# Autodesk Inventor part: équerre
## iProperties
Shininess: 64.0
Length Units: 11269
Angle Units: 11279
Time Units: 11290
Mass Units: 11283
Length Display Precision: 3
Angle Display Precision: 2
Compacted: True
Part Number: équerre
Document SubType Name: Modeling
Created: 2005-02
Material: Par défaut
Designer: LEGERET Philippe
Density: 0.0
Volumn: 0.0
Area: 0.0
PropertySet Name: Model Information
Control State: 0
Master: False
Checked Out: False
Author: LEGERET Philippe
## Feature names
1. Extrusion1
2. Chanfrein1 [Chamfer]
